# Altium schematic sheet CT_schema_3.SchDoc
size 307 x 169 mm
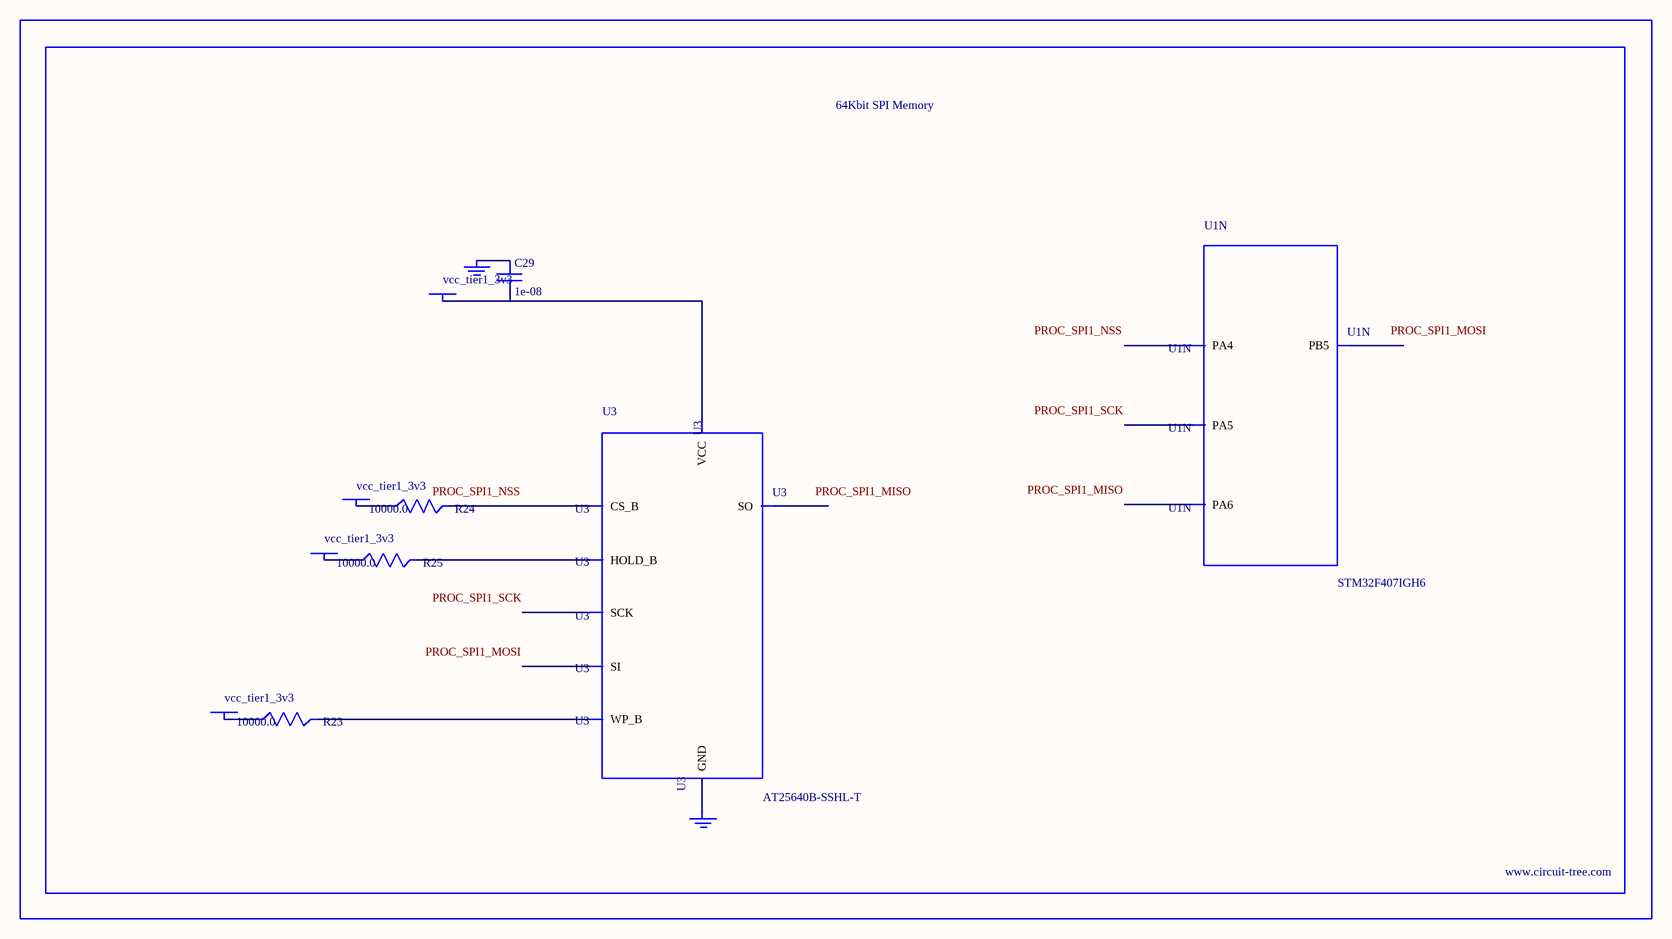
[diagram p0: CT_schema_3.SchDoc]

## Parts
BORDER2  (no value)
C29  1e-08  [C0402]
GND_INSTANCE_2_0  (no value)
GND_INSTANCE_2_1  (no value)
POWER_INSTANCE_2_0  vcc_tier1_3v3
POWER_INSTANCE_2_1  vcc_tier1_3v3
POWER_INSTANCE_2_2  vcc_tier1_3v3
POWER_INSTANCE_2_3  vcc_tier1_3v3
R23  10000.0  [R0603]
R24  10000.0  [R0603]
R25  10000.0  [R0603]
U1  STM32F407IGH6  [UFBGA176]  (part N of 18)
U3  AT25640B-SSHL-T  [SOIC-8]

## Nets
NetC29_1: C29.1 GND_INSTANCE_2_0.0(GND)
NetC29_2: C29.2 POWER_INSTANCE_2_3.0(PWR) U3.8(VCC)
NetGND_INSTANCE_2_1_0: GND_INSTANCE_2_1.0(GND) U3.4(GND)
NetPOWER_INSTANCE_2_0_0: POWER_INSTANCE_2_0.0(PWR) R24.1
NetPOWER_INSTANCE_2_1_0: POWER_INSTANCE_2_1.0(PWR) R23.1
NetPOWER_INSTANCE_2_2_0: POWER_INSTANCE_2_2.0(PWR) R25.1
NetR23_2: R23.2 U3.3(WP_B)
NetR24_2: R24.2 U3.1(CS_B)
NetR25_2: R25.2 U3.7(HOLD_B)

Not connected (* = marked no-connect by the designer): U1 A6(PB5) N4(PA4) P3(PA6) P4(PA5); U3 2(SO) 5(SI) 6(SCK)

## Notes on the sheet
- Labels drawn without touching a wire or pin: PROC_SPI1_MISO, PROC_SPI1_MOSI, PROC_SPI1_NSS, PROC_SPI1_SCK

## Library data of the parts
BORDER2 = BORDER_PAGE2
C29 = C0402C103K3RAC
GND_INSTANCE_2_0 GND_INSTANCE_2_1 = GND
POWER_INSTANCE_2_0-POWER_INSTANCE_2_3 = PWR
R23-R25 = RC0603JR-0710KL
